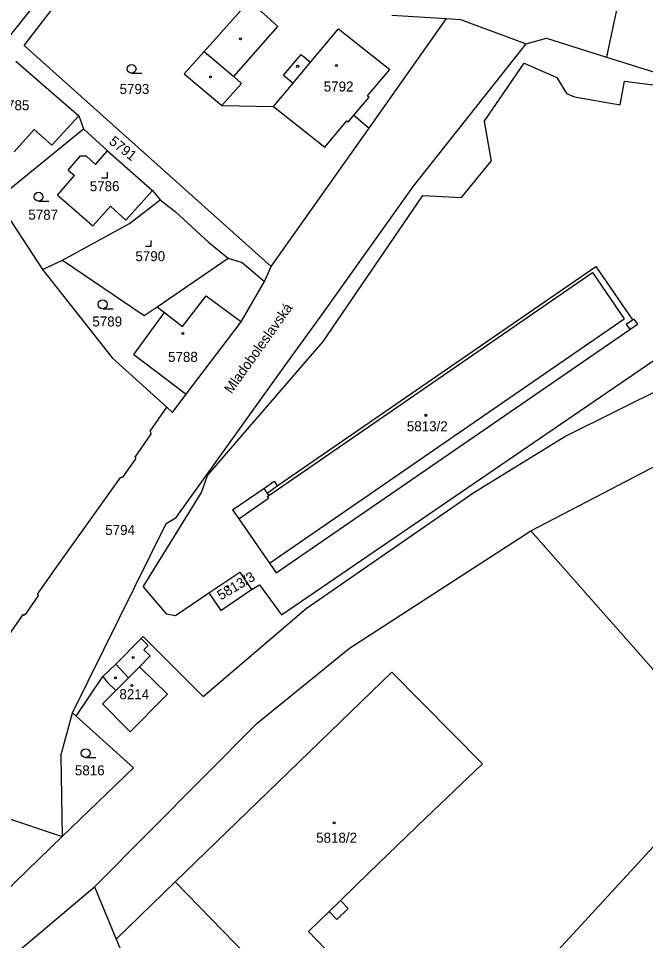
# Model space of a CAD drawing. Extents: x -717507 to -715515, y -957700 to -954941.
# Drawn here: x -715879.8 to -715773.2, y -955222.4 to -955065.8 of the extents above; entities that cross this region are included whole.
import ezdxf

# ---------------------------------------------------------------- set-up
doc = ezdxf.new("R2010")
doc.units = 0
for name, color, linetype in [('Hranice parcel', 7, 'Continuous'), ('Parcelní čísla', 7, 'Continuous'), ('Pop  PČ popisy', 7, 'Continuous'), ('Vnitřní kresba', 7, 'Continuous'), ('Značky budov', 7, 'Continuous'), ('Značky kultur', 7, 'Continuous')]:
    doc.layers.add(name, color=color, linetype=linetype)

msp = doc.modelspace()

# ---------------------------------------------------------------- linework, layer by layer
at = {"layer": 'Hranice parcel'}
for points in [[(-715775.97, -955054.15), (-715779.46, -955070.68)], [(-715882.86, -955070.77), (-715873.74, -955059.29)], [(-715878.79, -955070.34), (-715871.38, -955060.66)], [(-715848.23, -955071.39), (-715840.49, -955062.75)], [(-715816.32, -955065.2), (-715807.01, -955065.79)], [(-715808.07, -955067.28), (-715807.01, -955065.79)], [(-715807.01, -955065.79), (-715804.64, -955065.94)], [(-715804.64, -955065.94), (-715793.48, -955070.09)], [(-715820.18, -955084.36), (-715808.07, -955067.28)], [(-715793.48, -955070.09), (-715790.01, -955069.13)], [(-715790.01, -955069.13), (-715779.8, -955072.31)], [(-715878.79, -955070.34), (-715836.85, -955107.87)], [(-715851.62, -955075.17), (-715848.23, -955071.39)], [(-715812.62, -955094.26), (-715793.48, -955070.09)], [(-715779.46, -955070.68), (-715779.8, -955072.31)], [(-715880.23, -955073.03), (-715869.53, -955082.27)], [(-715779.8, -955072.31), (-715759.64, -955078.61)], [(-715851.62, -955075.17), (-715845.22, -955080.56)], [(-715845.22, -955080.56), (-715836.45, -955080.7)], [(-715836.45, -955080.7), (-715827.68, -955087.6)], [(-715869.53, -955082.27), (-715868.7, -955084.52)], [(-715823.74, -955083.36), (-715822.76, -955082.19)], [(-715822.76, -955082.19), (-715820.18, -955084.36)], [(-715827.68, -955087.6), (-715823.98, -955083.17)], [(-715823.98, -955083.17), (-715823.74, -955083.36)], [(-715883.51, -955096.5), (-715868.7, -955084.52)], [(-715868.7, -955084.52), (-715864.62, -955088.21)], [(-715836.85, -955107.87), (-715820.18, -955084.36)], [(-715866.68, -955090.56), (-715864.62, -955088.21)], [(-715864.62, -955088.21), (-715857.02, -955094.98)], [(-715871.32, -955091.5), (-715869.22, -955089.09)], [(-715869.22, -955089.09), (-715868.26, -955089.1)], [(-715868.26, -955089.1), (-715866.68, -955090.56)], [(-715871.32, -955091.5), (-715870.26, -955092.43)], [(-715873.14, -955095.74), (-715870.26, -955092.43)], [(-715861.52, -955099.99), (-715857.02, -955094.98)], [(-715857.02, -955094.98), (-715855.7, -955096.57)], [(-715828.06, -955115.85), (-715812.62, -955094.26)], [(-715883.51, -955096.5), (-715875.69, -955108.39)], [(-715873.14, -955095.74), (-715872.05, -955096.7)], [(-715872.05, -955096.7), (-715867.15, -955100.99)], [(-715867.15, -955100.99), (-715864.13, -955097.64)], [(-715864.13, -955097.64), (-715861.52, -955099.99)], [(-715860.92, -955100.58), (-715855.7, -955096.57)], [(-715855.7, -955096.57), (-715853.12, -955098.54)], [(-715853.12, -955098.54), (-715847.49, -955103.73)], [(-715872.27, -955106.78), (-715860.92, -955100.58)], [(-715847.49, -955103.73), (-715844.16, -955106.47)], [(-715875.69, -955108.39), (-715872.27, -955106.78)], [(-715872.27, -955106.78), (-715858.41, -955116.2)], [(-715856.22, -955114.71), (-715844.16, -955106.47)], [(-715844.16, -955106.47), (-715841.78, -955107.2)], [(-715841.78, -955107.2), (-715837.97, -955110.43)], [(-715875.69, -955108.39), (-715863.85, -955123.41)], [(-715837.97, -955110.43), (-715836.85, -955107.87)], [(-715835.8, -955145.14), (-715781.61, -955107.87)], [(-715781.61, -955107.87), (-715775.39, -955116.94)], [(-715841.92, -955117.27), (-715837.97, -955110.43)], [(-715858.41, -955116.2), (-715856.22, -955114.71)], [(-715856.22, -955114.71), (-715854.94, -955115.7)], [(-715860.19, -955122.8), (-715854.94, -955115.7)], [(-715834.35, -955124.55), (-715828.06, -955115.85)], [(-715775.39, -955116.94), (-715775.15, -955116.8)], [(-715775.15, -955116.8), (-715774.55, -955117.69)], [(-715851.26, -955129.54), (-715841.92, -955117.27)], [(-715775.86, -955118.56), (-715774.55, -955117.69)], [(-715835.97, -955159.91), (-715775.86, -955118.56)], [(-715860.19, -955122.8), (-715851.26, -955129.54)], [(-715863.85, -955123.41), (-715854.55, -955131.78)], [(-715852.99, -955150.51), (-715834.35, -955124.55)], [(-715786.91, -955136.74), (-715760.9, -955123.82)], [(-715853.57, -955132.65), (-715851.26, -955129.54)], [(-715857.37, -955135.84), (-715854.55, -955131.78)], [(-715854.55, -955131.78), (-715853.57, -955132.65)], [(-715859.97, -955140.24), (-715857.27, -955136.44)], [(-715857.37, -955135.84), (-715857.27, -955136.44)], [(-715802.36, -955146.26), (-715786.91, -955136.74)], [(-715859.97, -955140.24), (-715859.83, -955140.34)], [(-715859.94, -955140.5), (-715859.83, -955140.34)], [(-715862.03, -955143.66), (-715859.84, -955140.57)], [(-715859.94, -955140.5), (-715859.84, -955140.57)], [(-715792.68, -955152.77), (-715770.94, -955141.43)], [(-715865.36, -955147.84), (-715862.38, -955143.64)], [(-715862.38, -955143.64), (-715862.24, -955143.73)], [(-715862.24, -955143.73), (-715862.14, -955143.59)], [(-715862.14, -955143.59), (-715862.03, -955143.66)], [(-715838.08, -955145.56), (-715836.34, -955144.34)], [(-715836.34, -955144.34), (-715835.8, -955145.14)], [(-715843.38, -955149.22), (-715838.08, -955145.56)], [(-715830.88, -955165.98), (-715802.36, -955146.26)], [(-715873.57, -955159.34), (-715865.36, -955147.84)], [(-715843.38, -955149.22), (-715842.31, -955150.75)], [(-715854.7, -955151.55), (-715852.99, -955150.51)], [(-715842.31, -955150.75), (-715837.11, -955158.27)], [(-715870.62, -955183.71), (-715854.7, -955151.55)], [(-715823.53, -955172.69), (-715792.68, -955152.77)], [(-715792.68, -955152.77), (-715766.36, -955182.61)], [(-715837.11, -955158.27), (-715835.97, -955159.91)], [(-715876.54, -955163.55), (-715873.57, -955159.34)], [(-715847.42, -955163.32), (-715842.16, -955159.77)], [(-715842.16, -955159.77), (-715840.15, -955162.74)], [(-715878.6, -955166.99), (-715876.41, -955163.88)], [(-715876.54, -955163.55), (-715876.4, -955163.65)], [(-715876.52, -955163.81), (-715876.4, -955163.65)], [(-715876.52, -955163.81), (-715876.41, -955163.88)], [(-715847.42, -955163.32), (-715845.38, -955166.29)], [(-715845.38, -955166.29), (-715840.15, -955162.74)], [(-715881.63, -955170.85), (-715878.96, -955166.98)], [(-715878.96, -955166.98), (-715878.82, -955167.07)], [(-715878.82, -955167.07), (-715878.7, -955166.91)], [(-715878.7, -955166.91), (-715878.6, -955166.99)], [(-715848.39, -955180.9), (-715830.88, -955165.98)], [(-715863.24, -955175.43), (-715858.94, -955171.04)], [(-715858.94, -955171.04), (-715858.61, -955170.7)], [(-715858.94, -955171.04), (-715857.72, -955172.23)], [(-715858.61, -955170.7), (-715848.39, -955180.9)], [(-715858.47, -955173), (-715857.72, -955172.23)], [(-715858.47, -955173), (-715857.4, -955174.02)], [(-715839.19, -955185.44), (-715823.53, -955172.69)], [(-715859.18, -955175.86), (-715857.4, -955174.02)], [(-715865.42, -955177.52), (-715863.24, -955175.43)], [(-715859.18, -955175.86), (-715854.47, -955180.54)], [(-715870, -955184.26), (-715865.42, -955177.52)], [(-715865.42, -955177.52), (-715864.57, -955178.57)], [(-715864.57, -955178.57), (-715863.24, -955179.91)], [(-715865.52, -955182.18), (-715863.24, -955179.91)], [(-715860.81, -955186.91), (-715854.92, -955180.99)], [(-715854.92, -955180.99), (-715854.47, -955180.54)], [(-715865.52, -955182.18), (-715860.81, -955186.91)], [(-715872.59, -955190.97), (-715870.62, -955183.71)], [(-715870.62, -955183.71), (-715870, -955184.26)], [(-715870, -955184.26), (-715860.21, -955193)], [(-715866.85, -955213.22), (-715839.19, -955185.44)], [(-715872.59, -955190.97), (-715872.36, -955204.7)], [(-715872.36, -955204.7), (-715860.21, -955193)], [(-715882.47, -955201.27), (-715872.36, -955204.7)], [(-715882.14, -955214.19), (-715872.36, -955204.7)], [(-715793.97, -955230.46), (-715771.23, -955205.7)], [(-715863.19, -955222.13), (-715853.12, -955212.39)], [(-715853.12, -955212.39), (-715834.93, -955231.09)], [(-715879.52, -955223.94), (-715866.85, -955213.22)], [(-715866.85, -955213.22), (-715863.19, -955222.13)], [(-715863.19, -955222.13), (-715854.51, -955242.32)]]:
    msp.add_lwpolyline(points, dxfattribs=at)
at = {"layer": 'Vnitřní kresba'}
for points in [[(-715840.49, -955062.75), (-715835.69, -955067.13)], [(-715843.19, -955075.63), (-715835.69, -955067.13)], [(-715830.14, -955073.2), (-715825.37, -955067.54)], [(-715825.37, -955067.54), (-715816.66, -955074.42)], [(-715848.23, -955071.39), (-715843.19, -955075.63)], [(-715834.7, -955075.39), (-715831.73, -955071.86)], [(-715831.73, -955071.86), (-715830.14, -955073.2)], [(-715833.11, -955076.73), (-715830.14, -955073.2)], [(-715820.42, -955078.92), (-715816.66, -955074.42)], [(-715800.62, -955083.26), (-715793.8, -955073.35)], [(-715793.8, -955073.35), (-715788.26, -955075.76)], [(-715843.19, -955075.63), (-715841.88, -955076.78)], [(-715834.7, -955075.39), (-715833.11, -955076.73)], [(-715788.26, -955075.76), (-715786.6, -955078.52)], [(-715845.22, -955080.56), (-715841.88, -955076.78)], [(-715836.45, -955080.7), (-715833.11, -955076.73)], [(-715777.5, -955080.4), (-715776.78, -955076.42)], [(-715776.78, -955076.42), (-715759.64, -955078.61)], [(-715822.76, -955082.19), (-715820.19, -955079.11)], [(-715820.42, -955078.92), (-715820.19, -955079.11)], [(-715786.6, -955078.52), (-715785.27, -955079.08)], [(-715785.27, -955079.08), (-715777.5, -955080.4)], [(-715874.13, -955087.26), (-715869.53, -955082.27)], [(-715800.62, -955083.26), (-715799.45, -955089.97)], [(-715880.49, -955088.43), (-715877.12, -955084.62)], [(-715877.12, -955084.62), (-715874.13, -955087.26)], [(-715804.45, -955096.15), (-715799.45, -955089.97)], [(-715827.98, -955120.61), (-715811.06, -955095.83)], [(-715811.06, -955095.83), (-715804.45, -955096.15)], [(-715837.24, -955146.78), (-715782.18, -955108.9)], [(-715782.18, -955108.9), (-715776.8, -955116.79)], [(-715851.87, -955118.06), (-715847.86, -955112.84)], [(-715847.86, -955112.84), (-715842.06, -955117.16)], [(-715854.94, -955115.7), (-715851.87, -955118.06)], [(-715837.11, -955158.27), (-715776.8, -955116.79)], [(-715842.06, -955117.16), (-715841.92, -955117.27)], [(-715776.5, -955117.67), (-715775.39, -955116.94)], [(-715776.5, -955117.67), (-715775.86, -955118.56)], [(-715847.65, -955143.4), (-715827.98, -955120.61)], [(-715835.08, -955167.05), (-715770.62, -955123.08)], [(-715848.65, -955146.26), (-715847.65, -955143.4)], [(-715858.57, -955162.3), (-715848.65, -955146.26)], [(-715838.08, -955145.56), (-715837.51, -955146.36)], [(-715837.51, -955146.36), (-715835.8, -955145.14)], [(-715837.51, -955146.36), (-715837.24, -955146.78)], [(-715842.31, -955150.75), (-715837.29, -955147.25)], [(-715837.5, -955146.97), (-715837.24, -955146.78)], [(-715837.5, -955146.97), (-715837.29, -955147.25)], [(-715858.57, -955162.3), (-715854.69, -955166.86)], [(-715840.15, -955162.74), (-715838.81, -955161.97)], [(-715838.81, -955161.97), (-715835.08, -955167.05)], [(-715853.08, -955167.15), (-715847.42, -955163.32)], [(-715854.69, -955166.86), (-715853.08, -955167.15)], [(-715863.24, -955175.43), (-715861.08, -955177.76)], [(-715861.08, -955177.76), (-715859.18, -955175.86)], [(-715863.24, -955179.91), (-715861.08, -955177.76)], [(-715853.12, -955212.39), (-715816.3, -955176.79)], [(-715816.3, -955176.79), (-715800.91, -955192.36)], [(-715810.52, -955201.52), (-715800.91, -955192.36)], [(-715820.23, -955210.87), (-715810.52, -955201.52)], [(-715825.04, -955215.55), (-715820.23, -955210.87)], [(-715826.95, -955217.42), (-715825.04, -955215.55)], [(-715825.04, -955215.55), (-715823.71, -955216.92)], [(-715825.66, -955218.8), (-715823.71, -955216.92)], [(-715830.46, -955220.81), (-715826.95, -955217.42)], [(-715826.95, -955217.42), (-715825.66, -955218.8)], [(-715830.46, -955220.81), (-715827.68, -955223.71)]]:
    msp.add_lwpolyline(points, dxfattribs=at)
at = {"layer": 'Značky budov'}
for centre in [(-715842.05, -955069.2), (-715832.32, -955073.89), (-715825.7, -955073.74), (-715847.14, -955075.67), (-715851.84, -955119.27), (-715810.52, -955133.16), (-715860.28, -955174.27), (-715863.28, -955177.73), (-715860.52, -955179.03), (-715826.1, -955202.36)]:
    msp.add_circle(centre, 0.175, dxfattribs=at)
at = {"layer": 'Značky kultur'}
for points in [[(-715860.55, -955075.06), (-715858.8, -955075.06)], [(-715865.65, -955092.85), (-715864.65, -955092.85), (-715864.65, -955091.85)], [(-715876.38, -955096.78), (-715874.63, -955096.78)], [(-715858.2, -955104.44), (-715857.2, -955104.44), (-715857.2, -955103.44)], [(-715865.46, -955115.06), (-715863.71, -955115.06)], [(-715868.36, -955191.28), (-715866.61, -955191.28)]]:
    msp.add_lwpolyline(points, dxfattribs=at)
for centre, radius in [((-715860.55, -955074.31), 0.75), ((-715876.38, -955096.03), 0.75), ((-715865.46, -955114.31), 0.75), ((-715844.26, -955162.24), 0.175), ((-715868.36, -955190.53), 0.75)]:
    msp.add_circle(centre, radius, dxfattribs=at)

# ---------------------------------------------------------------- texts
at = {"layer": 'Parcelní čísla'}
for s, p in [('5793', (-715862.59, -955078.58)), ('5792', (-715827.89, -955078.16)), ('5785', (-715882.98, -955081.34)), ('5786', (-715867.66, -955095.09)), ('5787', (-715878.1, -955099.94)), ('5790', (-715859.9, -955106.98)), ('5789', (-715867.22, -955118.07)), ('5788', (-715854.35, -955124.08)), ('5813/2', (-715813.76, -955135.87)), ('5794', (-715865.03, -955153.48)), ('8214', (-715862.62, -955181.37)), ('5816', (-715870.19, -955194.3)), ('5818/2', (-715829.18, -955205.74))]:
    msp.add_text(s, height=1.7, dxfattribs=at).set_placement(p)
for s, rotation, p in [('5791', 321.8026, (-715864.52, -955086.92)), ('5813/3', 30.7002, (-715845.37, -955164.61))]:
    msp.add_text(s, height=1.7, rotation=rotation, dxfattribs=at).set_placement(p)
at = {"layer": 'Pop  PČ popisy'}
msp.add_text('Mladoboleslavská', height=1.7, rotation=54.6004, dxfattribs=at).set_placement((-715843.56, -955129.61))

doc.saveas('drawing.dxf')
